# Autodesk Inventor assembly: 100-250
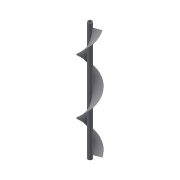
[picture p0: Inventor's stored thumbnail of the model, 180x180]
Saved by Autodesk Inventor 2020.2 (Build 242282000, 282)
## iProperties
Created: 2018-01
Part Number: 100-250
Document SubType Name: Konstrukcja spawana
Designer: F.Stasiak
Weld Material: Stal, miękka, spawana
Manager: www.cadconsulting.pl
Company: Fabian Stasiak CAD Consulting
Author: F.Stasiak
Subject: Zbiór ćwiczeń. Autodesk Inventor 2020. Kurs podstawowy
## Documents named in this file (3)
- C:\2020_Kurs_podstawowy\R6 Zespoły\Kolizja\100-250.iam
- C:\2020_Kurs_podstawowy\R6 Zespoły\Kolizja\100-251.ipt
- C:\2020_Kurs_podstawowy\R6 Zespoły\Kolizja\100-252.ipt
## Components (2 placed, 2 different names)
1. 100-251:1
2. 100-252:1
